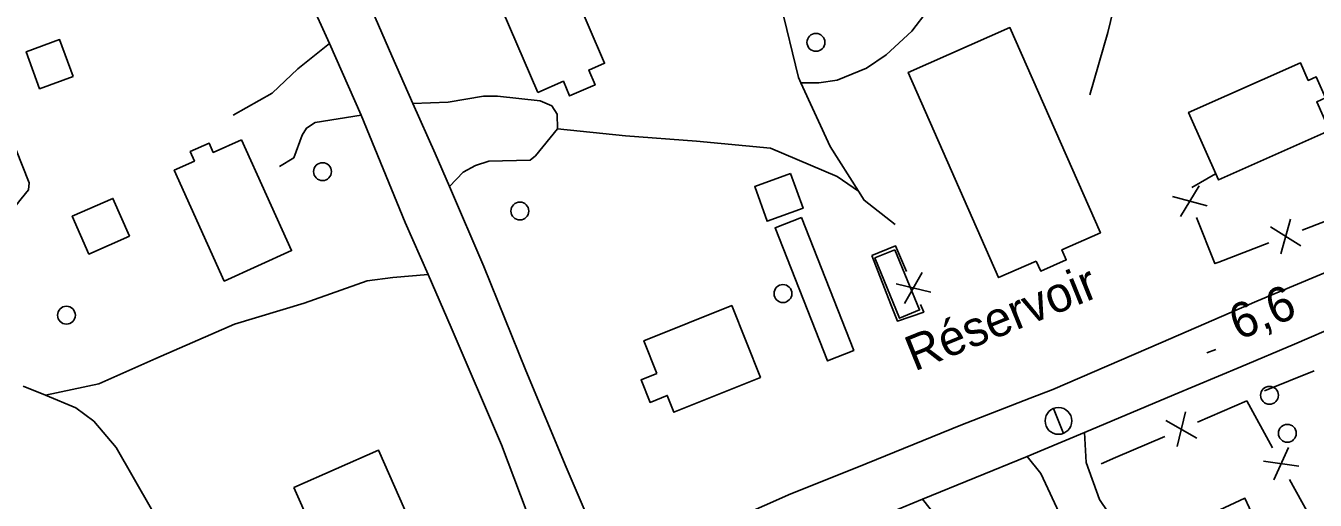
# Model space of a CAD drawing. Extents: x 362852 to 366875, y 5563573 to 5566479.
# Drawn here: x 364014.1 to 364158.5, y 5565014.1 to 5565067.1 of the extents above; entities that cross this region are included whole.
import ezdxf

# ---------------------------------------------------------------- set-up
doc = ezdxf.new("R2010")
doc.units = 0
for name, color, linetype in [('Niveau 19', 7, 'Continuous'), ('Niveau 21', 7, 'Continuous'), ('Niveau 22', 7, 'Continuous'), ('Niveau 3', 7, 'Continuous'), ('Niveau 31', 7, 'Continuous'), ('Niveau 33', 7, 'Continuous'), ('Niveau 36', 7, 'Continuous'), ('Niveau 37', 7, 'Continuous')]:
    doc.layers.add(name, color=color, linetype=linetype)

msp = doc.modelspace()

# ---------------------------------------------------------------- linework, layer by layer
at = {"layer": 'Niveau 19'}
for points in [[(364048.11, 5565065.15), (364044.58, 5565062.33), (364041.72, 5565059.63), (364037.36, 5565057.16)], [(364057.47, 5565058.45), (364061.41, 5565058.59), (364065.37, 5565059.28), (364066.92, 5565059.29), (364071.72, 5565058.74), (364073, 5565058.2), (364073.6, 5565057.28), (364073.65, 5565055.62), (364071.19, 5565052.61), (364070.59, 5565052.11), (364065.95, 5565052.02), (364064.46, 5565051.54), (364063.09, 5565050.78), (364061.55, 5565049.19)], [(364042.53, 5565051.43), (364044.13, 5565052.4), (364045.06, 5565054.93), (364045.56, 5565055.7), (364046.54, 5565056.35), (364051.68, 5565057.14)], [(364132.64, 5565021.68), (364132.84, 5565018.34), (364134.33, 5565014.2), (364136.26, 5565011.31)], [(364126.22, 5565019), (364127.77, 5565017.08), (364130.08, 5565012.15), (364131.36, 5565007.75)]]:
    msp.add_lwpolyline(points, dxfattribs=at)
at = {"layer": 'Niveau 21'}
for points in [[(364076.64, 5565013.12), (364074.62, 5565017.79), (364070.1, 5565028.61), (364065.41, 5565040.22), (364061.55, 5565049.19), (364059.97, 5565052.86), (364057.47, 5565058.45), (364055.09, 5565063.79), (364051.48, 5565072.13), (364051.02, 5565073.18), (364046.88, 5565082.7), (364042.96, 5565092.44), (364041.99, 5565095.2), (364042.14, 5565097.76), (364043.7, 5565101.27), (364044.45, 5565102.2), (364045.71, 5565102.78), (364047.2, 5565103.4)], [(364070.9, 5565011.01), (364067.4, 5565020.3), (364061.76, 5565033.41), (364059.17, 5565039.33), (364056.61, 5565045.17), (364051.68, 5565057.14), (364048.11, 5565065.15), (364045.85, 5565070.21), (364045.3, 5565071.49), (364040.9, 5565081.84), (364036.89, 5565091.26), (364035.53, 5565093.07), (364034.32, 5565093.76), (364032.47, 5565094.63), (364030.15, 5565095.12), (364028.6, 5565095.24), (364026.65, 5565095.13), (364021.99, 5565093.4), (364010.11, 5565087.96)], [(364089.07, 5565003.85), (364111.25, 5565012.88), (364114.52, 5565014.22), (364126.22, 5565019), (364128.1, 5565019.77), (364132.64, 5565021.68), (364142.64, 5565025.9), (364150.13, 5565029.03), (364156.16, 5565031.56), (364161.35, 5565033.78), (364165.7, 5565035.64), (364170.6, 5565037.73), (364181.51, 5565042.27)], [(364163.1, 5565041.02), (364151.93, 5565036.37), (364141.18, 5565031.71), (364129.09, 5565026.5), (364126.57, 5565025.52), (364118.8, 5565022.49), (364107.14, 5565017.77), (364099.77, 5565014.84), (364090.93, 5565010.92)]]:
    msp.add_lwpolyline(points, dxfattribs=at)
at = {"layer": 'Niveau 22'}
for points in [[(364073.94, 5565115.02), (364074.85, 5565111.09), (364077.11, 5565104.04), (364080.28, 5565096), (364081.46, 5565093.86), (364084.25, 5565089.75), (364086.1, 5565087.51), (364092.68, 5565081.49), (364094.4, 5565079.39), (364095.79, 5565076.89), (364098.65, 5565069.47), (364100.61, 5565061.36), (364100.88, 5565060.77), (364104.18, 5565053.64), (364107.33, 5565048.66), (364107.97, 5565047.65), (364111.46, 5565044.94)], [(364004.84, 5565085.79), (364006.98, 5565083.35), (364008.98, 5565080.51), (364010.66, 5565077.23), (364011.68, 5565073.65), (364011, 5565069.94), (364009.96, 5565066.07), (364009.72, 5565062.66), (364010.27, 5565060.7), (364012.32, 5565055.13), (364014.51, 5565049.59), (364014.45, 5565048.81), (364013.62, 5565047.79), (364011.78, 5565045.5), (364010.2, 5565043.42), (364007.69, 5565042.08), (364005.44, 5565041.47), (363998.46, 5565038.64), (363993.64, 5565036.63), (363991.74, 5565036.1), (363990.19, 5565035.9), (363987.15, 5565035.11)], [(364133.23, 5565059.43), (364135.27, 5565066.38), (364137.4, 5565075.17), (364138.97, 5565079.16), (364139.86, 5565081.28), (364140.08, 5565082.74), (364139.88, 5565084.36)], [(364100.88, 5565060.77), (364102.92, 5565060.75), (364104.96, 5565061.08), (364108.25, 5565062.41), (364110.46, 5565063.88), (364113.33, 5565066.53), (364116.98, 5565071.34), (364118.71, 5565073.14), (364122.98, 5565076.67), (364128.82, 5565080.84)], [(364073.65, 5565055.62), (364081.25, 5565054.86), (364089.22, 5565054.25), (364097.48, 5565053.48), (364104.95, 5565050.29), (364107.33, 5565048.66)], [(364016.32, 5565025.84), (364022.3, 5565027.13), (364028.7, 5565029.94), (364037.51, 5565033.78), (364045.3, 5565036.14), (364052.36, 5565038.62), (364055.2, 5565039.02), (364059.17, 5565039.33)], [(364028.22, 5565013.11), (364024.26, 5565020.01), (364021.73, 5565022.93), (364019.75, 5565024.43), (364016.32, 5565025.84), (364013.83, 5565026.87)], [(364114.52, 5565014.22), (364116.36, 5565011.87), (364121.61, 5565007.53), (364130.7, 5565001), (364137.29, 5564997.17), (364139.5, 5564996.02), (364141.27, 5564994.44), (364142.69, 5564992.54), (364144.4, 5564989.51), (364148.49, 5564983.66), (364153.41, 5564977.77), (364159.02, 5564972.34), (364161.37, 5564971.39)]]:
    msp.add_lwpolyline(points, dxfattribs=at)
at = {"layer": 'Niveau 3'}
msp.add_line((364146.35, 5565030.58), (364147.33, 5565030.97), dxfattribs=at)
at = {"layer": 'Niveau 31'}
for points in [[(364071.45, 5565059.7), (364065.93, 5565072.51), (364073.43, 5565075.74), (364078.93, 5565062.96), (364077.14, 5565062.19), (364077.85, 5565060.53), (364075.01, 5565059.31), (364074.31, 5565060.94), (364071.45, 5565059.7)], [(364127.24, 5565040.85), (364123.03, 5565038.99), (364112.92, 5565061.93), (364124.3, 5565066.95), (364134.42, 5565044.01), (364130.11, 5565042.11), (364130.6, 5565040.98), (364127.74, 5565039.72), (364127.24, 5565040.85)], [(364019.42, 5565061.46), (364015.68, 5565060.11), (364014.18, 5565064.24), (364017.92, 5565065.6), (364019.42, 5565061.46)], [(364160.08, 5565055.43), (364147.63, 5565049.91), (364144.29, 5565057.46), (364156.82, 5565063.01), (364157.7, 5565061.03), (364158.58, 5565061.42), (364159.62, 5565059.08), (364158.65, 5565058.65), (364160.08, 5565055.43)], [(364038.29, 5565054.41), (364043.89, 5565042.01), (364036.34, 5565038.6), (364030.74, 5565051), (364033.01, 5565052.02), (364032.54, 5565053.08), (364034.65, 5565054.03), (364035.12, 5565052.99), (364038.29, 5565054.41)], [(364099.75, 5565050.63), (364101.15, 5565046.74), (364097.12, 5565045.3), (364095.73, 5565049.19), (364099.75, 5565050.63)], [(364025.74, 5565043.62), (364021.19, 5565041.63), (364019.34, 5565045.86), (364023.88, 5565047.85), (364025.74, 5565043.62)], [(364100.95, 5565045.73), (364106.81, 5565030.85), (364103.87, 5565029.69), (364098, 5565044.57), (364100.95, 5565045.73)], [(364084.78, 5565028.28), (364083.32, 5565031.93), (364093.15, 5565035.87), (364096.37, 5565027.84), (364086.68, 5565023.95), (364085.93, 5565025.82), (364084.01, 5565025.05), (364083, 5565027.57), (364084.78, 5565028.28)], [(364044.15, 5565015.53), (364053.61, 5565019.71), (364057.13, 5565011.76), (364054.57, 5565010.62), (364055.08, 5565009.46), (364052.65, 5565008.39), (364052.26, 5565009.28), (364047.79, 5565007.3), (364044.15, 5565015.53)], [(364138.12, 5565008.53), (364150.6, 5565014.33), (364154, 5565007.03), (364141.49, 5565001.22), (364140.64, 5565003.05), (364139.67, 5565002.6), (364138.63, 5565004.83), (364139.62, 5565005.29), (364138.12, 5565008.53)]]:
    msp.add_lwpolyline(points, dxfattribs=at)
at = {"layer": 'Niveau 33'}
msp.add_lwpolyline([(364111.42, 5565042.11), (364114.18, 5565035.38), (364111.94, 5565034.46), (364109.18, 5565041.19), (364111.42, 5565042.11)], dxfattribs=at)
at = {"layer": 'Niveau 36'}
msp.add_line((364130.29, 5565021.57), (364129.17, 5565024.35), dxfattribs=at)
for centre, radius in [((364102.58, 5565065.29), 1), ((364047.35, 5565050.84), 1), ((364069.44, 5565046.44), 1), ((364098.89, 5565037.21), 1), ((364018.68, 5565034.79), 1), ((364153.35, 5565025.84), 1), ((364129.73, 5565022.98), 1.5), ((364155.35, 5565021.59), 1)]:
    msp.add_circle(centre, radius, dxfattribs=at)
at = {"layer": 'Niveau 37'}
for p, q in [((364144.66, 5565049.07), (364147.32, 5565050.61)), ((364143.4, 5565045.84), (364145.48, 5565049.26)), ((364142.51, 5565048.06), (364146.37, 5565047.03)), ((364162.62, 5565046.46), (364157.02, 5565044.31)), ((364156.85, 5565042.53), (364153.46, 5565044.66)), ((364154.61, 5565041.67), (364155.7, 5565045.52)), ((364153.28, 5565042.88), (364147.68, 5565040.73)), ((364110.98, 5565035.97), (364108.84, 5565041.46)), ((364114.49, 5565039.56), (364112.49, 5565036.1)), ((364115.43, 5565037.35), (364111.55, 5565038.3)), ((364152.79, 5565026.34), (364158.35, 5565028.59)), ((364150.82, 5565025.22), (364145.31, 5565022.84)), ((364150.82, 5565025.22), (364153.69, 5565019.95)), ((364145.22, 5565021.06), (364141.74, 5565023.04)), ((364143.01, 5565020.1), (364143.95, 5565023.99)), ((364141.64, 5565021.25), (364136.13, 5565018.87)), ((364136.13, 5565018.87), (364134.52, 5565018.17)), ((364155.48, 5565020.02), (364153.82, 5565016.38)), ((364156.63, 5565017.91), (364152.67, 5565018.49))]:
    msp.add_line(p, q, dxfattribs=at)
for points in [[(364147.68, 5565040.73), (364147.25, 5565040.56), (364145.18, 5565045.7)], [(364108.84, 5565041.46), (364111.47, 5565042.56), (364112.71, 5565039.66)], [(364114.28, 5565035.99), (364114.64, 5565035.15), (364111.7, 5565034.13), (364110.98, 5565035.97)], [(364155.61, 5565016.44), (364157.76, 5565012.5), (364158.39, 5565011.13)]]:
    msp.add_lwpolyline(points, dxfattribs=at)

# ---------------------------------------------------------------- texts
at = {"layer": 'Niveau 3'}
msp.add_text('6,6  ', height=3.93, rotation=22.09, dxfattribs=at).set_placement((364149.87, 5565031.95))
at = {"layer": 'Niveau 33'}
msp.add_text('Réservoir', height=3.93, rotation=22.09, dxfattribs=at).set_placement((364113.61, 5565028.48))

doc.saveas('drawing.dxf')
